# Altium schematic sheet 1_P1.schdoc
size 309 x 223 mm; Symbol: Sheet-Symbol_A4; Device: Sheet-Symbol_A4; Convert to PCB: yes; Add into BOM: yes; @Project Name: Fly_Handle2; @Page Count: 1; @Update Date: 2022-08-23; @Create Date: 2022-08-22; @Schematic Name: Schematic2; @Page No: 1; @Page Name: P1
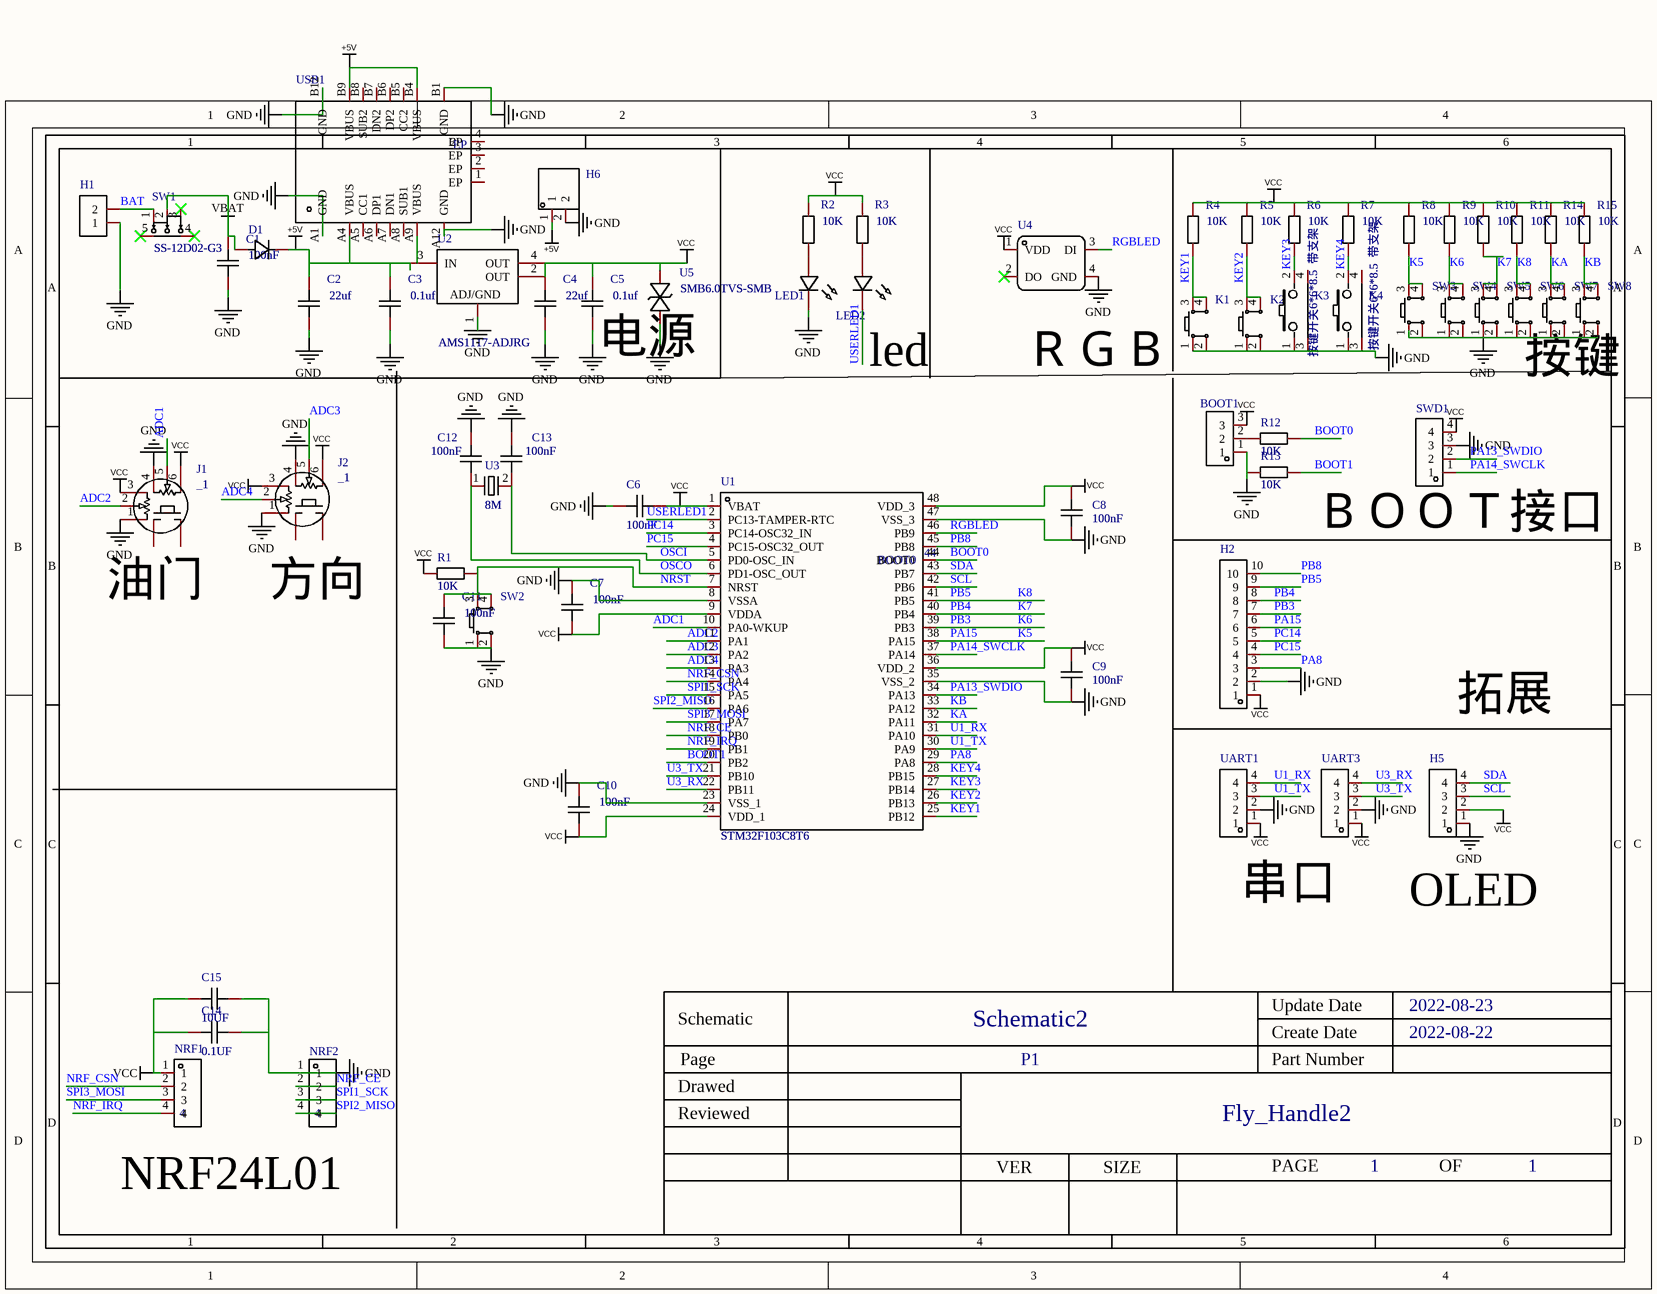
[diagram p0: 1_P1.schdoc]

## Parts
BOOT1  HDR-F_2.54_1x3P  [HDR-TH_3P-P2.54-V-F]  (value not drawn)
C1  100nF  [C0603]
C2  22uf  [C0603]
C3  0.1uf  [C0603]
C4  22uf  [C0603]
C5  0.1uf  [C0603]
C6  100nF  [C0603]
C7  100nF  [C0603]
C8  100nF  [C0603]
C9  100nF  [C0603]
C10  100nF  [C0603]
C11  100nF  [C0603]
C12  100nF  [C0603]
C13  100nF  [C0603]
C14  0.1UF  [C0603]
C15  10UF  [C0603]
D1  1N4007  [SMA_L4.4-W2.8-LS5.4-RD]  (value not drawn)
H1  HDR-F_2.54_1x2P  [HDR-TH_2P-P2.54-V-F]  (value not drawn)
H2  HDR-F_2.54_1x10P  [HDR-TH_10P-P2.54-V-F]  (value not drawn)
H5  HDR-F_2.54_1x4P  [HDR-TH_4P-P2.54-V-F]  (value not drawn)
H6  HDR-M_2.54_1x2P  [HDR-TH_2P-P2.54-V-M-1]  (value not drawn)
J1  _1  [摇杆带确认16*16]
J2  _1  [摇杆带确认16*16]
K1  Key_SMD_6x6x6.5  [SW-SMD_4P-L6.0-W6.0-P4.50-LS9.0-2]  (value not drawn)
K2  Key_SMD_6x6x6.5  [SW-SMD_4P-L6.0-W6.0-P4.50-LS9.0-2]  (value not drawn)
K3  按键开关6*6*8.5  带支架  [KEY-TH_C61279]
K4  按键开关6*6*8.5  带支架  [KEY-TH_C61279]
LED1  LED_0603-R  [LED0603-RD_BLUE]  (value not drawn)
LED2  LED_0603-R  [LED0603-RD_BLUE]  (value not drawn)
NRF1  NAME: 4  [HDR-TH_4P-P2.54-V-F]  (hidden comment: HDR-F_2.54_1x4P)
NRF2  NAME: 4  [HDR-TH_4P-P2.54-V-F]  (hidden comment: HDR-F_2.54_1x4P)
R1  10K  [R0603]
R2  10K  [R0603]
R3  10K  [R0603]
R4  10K  [R0603]
R5  10K  [R0603]
R6  10K  [R0603]
R7  10K  [R0603]
R8  10K  [R0603]
R9  10K  [R0603]
R10  10K  [R0603]
R11  10K  [R0603]
R12  10K  [R0603]
R13  10K  [R0603]
R14  10K  [R0603]
R15  10K  [R0603]
SW1  SS-12D02-G3  [SW-TH_SS-12D02-G3]
SW2  Key_SMD_6x6x6.5  [SW-SMD_4P-L6.0-W6.0-P4.50-LS9.0-2]  (value not drawn)
SW3  Key_SMD_6x6x6.5  [SW-SMD_4P-L6.0-W6.0-P4.50-LS9.0-2]  (value not drawn)
SW4  Key_SMD_6x6x6.5  [SW-SMD_4P-L6.0-W6.0-P4.50-LS9.0-2]  (value not drawn)
SW5  Key_SMD_6x6x6.5  [SW-SMD_4P-L6.0-W6.0-P4.50-LS9.0-2]  (value not drawn)
SW6  Key_SMD_6x6x6.5  [SW-SMD_4P-L6.0-W6.0-P4.50-LS9.0-2]  (value not drawn)
SW7  Key_SMD_6x6x6.5  [SW-SMD_4P-L6.0-W6.0-P4.50-LS9.0-2]  (value not drawn)
SW8  Key_SMD_6x6x6.5  [SW-SMD_4P-L6.0-W6.0-P4.50-LS9.0-2]  (value not drawn)
SWD1  HDR-F_2.54_1x4P  [HDR-TH_4P-P2.54-V-F]  (value not drawn)
U1  STM32F103C8T6  NAME: BOOT0  NUMBER: 44  [LQFP-48_L7.0-W7.0-P0.50-LS9.0-BL]
U2  AMS1117-ADJRG  [SOT-223-3_L6.4-W3.5-P2.30-LS7.0-BR]
U3  8M  [HC-49S_L11.0-W4.7-P4.88]
U4  rgb-5050  [LED-SMD_4P-L5.0-W5.0-BL_XL-5050RGBC]  (value not drawn)
U5  SMB6.0TVS-SMB  [SMB_L4.3-W3.6-LS5.4-BI]
UART1  HDR-F_2.54_1x4P  [HDR-TH_4P-P2.54-V-F]  (value not drawn)
UART3  HDR-F_2.54_1x4P  [HDR-TH_4P-P2.54-V-F]  (value not drawn)
USB1  NAME: EP  [USB-C-SMD_KH-TYPE-C-16P]  (hidden comment: USB_TYPE-C-16P)

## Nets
+5V: C2.2 C3.2 D1.1(K) H6.1 U2.3(IN) USB1.A4(VBUS) USB1.B4(VBUS) USB1.B9(VBUS)
GND: BOOT1.1 C1.1 C2.1 C3.1 C4.1 C5.1 C6.1 C7.2 C8.2 C9.2 C10.2 C11.1 C12.2 C13.2 C14.2 C15.2 H1.1 H2.2 H5.1 H6.2 J1.1 J1.4 J2.1 J2.4 K1.1 K1.2 K2.1 K2.2 K3.1 K3.3 K4.1 K4.3 LED1.1(C) NRF2.1 R13.1 SW2.1 SW2.2 SW3.1 SW3.2 SW4.1 SW4.2 SW5.1 SW5.2 SW6.1 SW6.2 SW7.1 SW7.2 SW8.1 SW8.2 SWD1.3 U1.8(VSSA) U1.23(VSS_1) U1.35(VSS_2) U1.47(VSS_3) U2.1(ADJ/GND) U4.4(GND) U5.2(A) UART1.2 UART3.2 USB1.A1(GND) USB1.A12(GND) USB1.B1(GND) USB1.B12(GND)
VBAT: C1.2 D1.2(A) SW1.2
VCC: BOOT1.3 C4.2 C5.2 C6.2 C7.1 C8.1 C9.1 C10.1 C14.1 C15.1 H2.1 H5.2 J1.3 J1.6 J2.3 J2.6 NRF1.1 R1.1 R2.1 R3.2 R4.2 R5.2 R6.2 R7.2 R8.2 R9.2 R10.2 R11.2 R14.2 R15.2 SWD1.4 U1.1(VBAT) U1.9(VDDA) U1.24(VDD_1) U1.36(VDD_2) U1.48(VDD_3) U2.2(OUT) U2.4(OUT) U4.1(VDD) U5.1(C) UART1.1 UART3.1
ADC1: J1.5 U1.10(PA0-WKUP)
ADC2: J1.2 U1.11(PA1)
ADC3: J2.5 U1.12(PA2)
ADC4: J2.2 U1.13(PA3)
BAT: H1.2 SW1.1
BOOT0: R12.2 U1.44(BOOT0)
BOOT1: R13.2 U1.20(PB2)
K5: H2.6 R8.1 SW3.3 SW3.4 U1.38(PA15)  [also labelled PA15]
K6: H2.7 R9.1 SW4.3 SW4.4 U1.39(PB3)  [also labelled PB3]
K7: H2.8 R10.1 SW5.3 SW5.4 U1.40(PB4)  [also labelled PB4]
K8: H2.9 R11.1 SW6.3 SW6.4 U1.41(PB5)  [also labelled PB5]
KA: R14.1 SW7.3 SW7.4 U1.32(PA11)
KB: R15.1 SW8.3 SW8.4 U1.33(PA12)
KEY1: K1.3 K1.4 R4.1 U1.25(PB12)
KEY2: K2.3 K2.4 R5.1 U1.26(PB13)
KEY3: K3.2 R6.1 U1.27(PB14)
KEY4: K4.2 R7.1 U1.28(PB15)
NRF_CE: NRF2.2 U1.18(PB0)
NRF_CSN: NRF1.2 U1.14(PA4)
NRF_IRQ: NRF1.4 U1.19(PB1)
NRST: C11.2 R1.2 SW2.3 SW2.4 U1.7(NRST)
OSCI: C13.1 U1.5(PD0-OSC_IN) U3.2(GND)
OSCO: C12.1 U1.6(PD1-OSC_OUT) U3.1
PA8: H2.3 U1.29(PA8)
PA13_SWDIO: SWD1.2 U1.34(PA13)
PA14_SWCLK: SWD1.1 U1.37(PA14)
PB8: H2.10 U1.45(PB8)
PC14: H2.5 U1.3(PC14-OSC32_IN)
PC15: H2.4 U1.4(PC15-OSC32_OUT)
RGBLED: U1.46(PB9) U4.3(DI)
SCL: H5.3 U1.42(PB6)
SDA: H5.4 U1.43(PB7)
SPI1_SCK: NRF2.3 U1.15(PA5)
SPI2_MISO: NRF2.4 U1.16(PA6)
SPI3_MOSI: NRF1.3 U1.17(PA7)
U1_RX: U1.31(PA10) UART1.4
U1_TX: U1.30(PA9) UART1.3
U3_RX: U1.22(PB11) UART3.4
U3_TX: U1.21(PB10) UART3.3
USERLED1: LED2.1(C) U1.2(PC13-TAMPER-RTC)
NetBOOT1_2: BOOT1.2 R12.1
NetLED1_2: LED1.2(A) R2.2
NetLED2_2: LED2.2(A) R3.1

Not connected (* = marked no-connect by the designer): J1 J1 J2; J2 J1 J2; K3 4; K4 4; SW1 3* 4* 5*; U4 2(DO)*; USB1 1(EP) 2(EP) 3(EP) 4(EP) A5(CC1) A6(DP1) A7(DN1) A8(SUB1) A9(VBUS) B5(CC2) B6(DP2) B7(DN2) B8(SUB2)

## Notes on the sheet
- 电源
- (near LED2) led
- (near U4) ＲＧＢ
- 按键
- (near SWD1) ＢＯＯＴ接口
- (near J1) 油门
- (near J2) 方向
- 拓展
- (near UART1) 串口
- (near H5) OLED
- NRF24L01

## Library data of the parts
BOOT1 = HDR-F_2.54_1x3P: Symbol: PM254V-11-03-H85; Convert to PCB: yes
C1 C2 C4 C6-C13 = CAP_0603: 容值:100nF;精度:±10%;额定电压:50V;温度系数:X7R;; Symbol: C1210X7R475K630NT; Convert to PCB: yes
C3 C5 C14 C15 = CAP_0603: 容值:100nF;精度:±10%;额定电压:50V;温度系数:X7R;; Symbol: C1210X7R475K630NT; Convert to PCB: yes; Value: 100nF
D1 = 1N4007: 二极管配置:独立式;直流反向耐压(Vr):1kV;平均整流电流(Io):1A;正向压降(Vf):1.1V@1A;反向电流(Ir):5A@1kV;; Symbol: D_1N4007; Add into BOM: yes
H1 = HDR-F_2.54_1x2P: Symbol: Header-Female-2.54_1x2; Convert to PCB: yes
H2 = HDR-F_2.54_1x10P: Symbol: X5511FV-10-C70D30-1000; Add into BOM: yes
H5 NRF1 NRF2 SWD1 UART1 UART3 = HDR-F_2.54_1x4P: Symbol: 2.54-1*4P母; Convert to PCB: yes
H6 = HDR-M_2.54_1x2P: Symbol: 210S-1*2P L=11.6MMGold-plated black; Convert to PCB: yes
J1 J2 = 遥杆16*16带确认: 遥杆带确认16*16; Symbol: 遥杆带确认; Add into BOM: yes; Origin Footprint: __2
K1 K2 SW2-SW8 = Key_SMD_6x6x6.5: 触点电流:50mA;额定电压(DC):12V;电路结构:单刀单掷;安装方式:立贴;按钮形状:圆形按钮;带灯:-;开关长度:6mm;开关宽度:6mm;开关高度:6.5mm;; Symbol: 轻触按键; Convert to PCB: yes
K3 K4 = 按键开关6*6*8.5  带支架: Symbol: button6*6*8.5 With stent; Add into BOM: yes
LED1 LED2 = LED_0603-R: 发光颜色:红灯;二极管配置:-;透镜颜色:无色透明;主波长:617.5nm;峰值波长:632nm;色温:-;光通量(25时):-;测试电流:5mA;正向电压(VF):2.2V;发光强度:28.5mcd;功率:60mW;发光角度:120°;安装方式:-;工作温度:-40~+85;; Symbol: LED_R; Convert to PCB: yes
R1-R15 = Res_0603: Symbol: 电阻; Convert to PCB: yes
SW1 = SS-12D02-G3: Manufacturer: USAKRO(美韩); Add into BOM: yes
U1 = STM32F103C8T6: CPU位数:32-Bit;ROM类型:FLASH;CPU内核:ARM® Cortex®-M3;主频（MAX):72MHz;工作电压:2V ~ 3.6V;; Manufacturer: ST(意法半导体); Add into BOM: yes; Core Size: 32-Bit; Program Memory Type: FLASH; Speed: 72MHz; Program Memory Size: 64KB; RAM Size: 20KB; Number of I/O: 37; A/D: 10x12bit; D/A: 0; PWM: 13; UART/USART: 3 USART; SPI: 2; USB Device: 1
U2 = AMS1117-ADJRG: 低压差线性稳压器 15V耐压 800MA电流低压差线性稳压(LDO); Manufacturer: HGC(深圳汉芯); Add into BOM: yes
U3 = 直插晶振: Add into BOM: yes
U4 = rgb-5050: Manufacturer: XINGLIGHT(成兴光); Symbol: XL-5050RGBC-WS2812B; Add into BOM: yes
U5 = SMB6.0TVS-SMB: Add into BOM: yes
USB1 = USB_TYPE-C-16P: 连接器类型:Type-C;标准:-;公母:母座;触点数量:16;端口数量:1;安装方式:卧贴;额定电流 - 电源:3A;工作温度范围:-40~+85;; Symbol: KH-TYPE-C-16P; Add into BOM: yes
